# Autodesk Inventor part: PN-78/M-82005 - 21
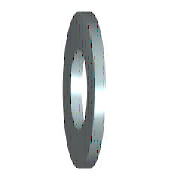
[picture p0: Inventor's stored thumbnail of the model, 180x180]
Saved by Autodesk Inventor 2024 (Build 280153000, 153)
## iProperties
IsCustomPart: 0
Company: ATC
Created: 2023-03
Part Number: PN-78/M-82005 - 21
Material: Stal, miękka
Description: Podkładki okrągłe, szereg nieobrobiony
Document SubType Name: Modeling
Standard: PN-78/M-82005
Designer: Andrzej Jaskulski
Standards Organization: PN
Language: pl-PL
Size Designation: 21
Categories: <MemberInstance><Categories><Category DisplayName="Mocowania" InternalName="e4da775c-781d-43d5-af7c-5136215cf5a6" Mnemonic="FSTN"><Category DisplayName="Podkład
Density: 7.85 g/cm^3
Appearance: Częściowo polerowany
Checked By: A.J.
Engr Approved By: Andrzej Jaskulski
Mfg Approved By: Andrzej Jaskulski
Authority: A.J.
Author: Andrzej Jaskulski
Title: A.J.: Kurs R2024-MEP
Revision Number: 1/24
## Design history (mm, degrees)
workaxis "Work Axis1"
workplane "Work Plane1"
body "Solid1"
sketch "Szkic"
  geometry: C1 r 18.5 at (0, 0); C2 r 10.5 at (0, 0); 1 further point
  constraints: 2 centre point, 2 coincident
  dimensions: "d0" = 21 diameter of C2 (= SD1); "d1" = 37 diameter of C1 (= SD2)
extrude "Bryła" new body sketch "Szkic" distance "d2" = 3 (= SD); taper "d3" = 0 deg
other parameters: "SD1" = 21 [user parameter; used in 1 equation term], "SD2" = 37 [user parameter; used in 1 equation term], "SD" = 3 [user parameter; used in 1 equation term], "d4" = 0, "d5" = 0, "d6" = 0, "d7" = 0
